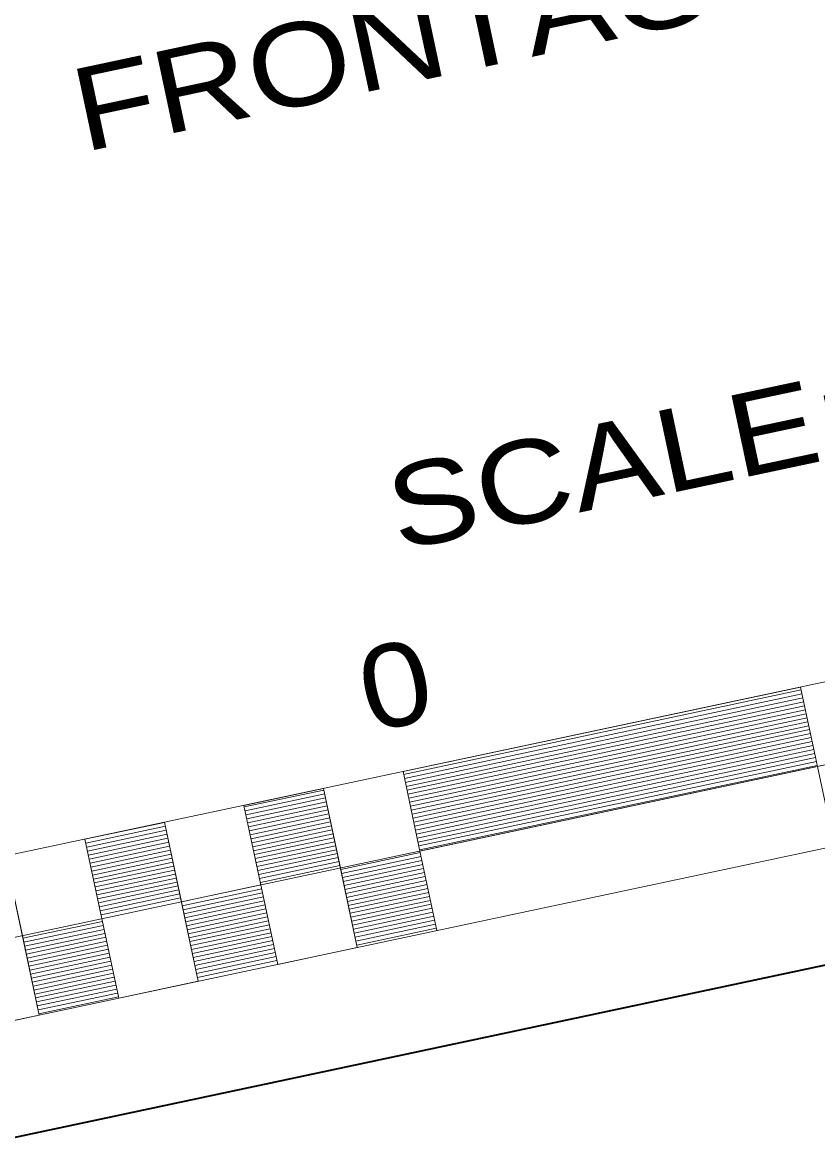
# Model space of a CAD drawing. Extents: x 2357218 to 2371708, y 6973728 to 6980157.
# Drawn here: x 2358141.4 to 2358239.3, y 6974159.6 to 6974296.3 of the extents above; entities that cross this region are included whole.
import ezdxf
from ezdxf.enums import TextEntityAlignment as Align

# ---------------------------------------------------------------- set-up
doc = ezdxf.new("R2010")
doc.units = 0
doc.header["$LTSCALE"] = 2
doc.layers.add('62', color=7, linetype='Continuous', lineweight=13)
doc.layers.add('63', color=7, linetype='Continuous', lineweight=13)

msp = doc.modelspace()

# ---------------------------------------------------------------- linework, layer by layer
at = {"layer": '62', "lineweight": 35}
msp.add_line((2358706.979, 6974279.557), (2358070.155, 6974144.195), dxfattribs=at)
at = {"layer": '62'}
for p, q in [((2358090.44, 6974183.356), (2358481.753, 6974266.532)), ((2358092.52, 6974173.573), (2358483.832, 6974256.749)), ((2358237.181, 6974214.547), (2358239.262, 6974204.763)), ((2358188.343, 6974203.797), (2358237.256, 6974214.195)), ((2358188.446, 6974203.309), (2358237.361, 6974213.706)), ((2358188.551, 6974202.819), (2358237.464, 6974213.216)), ((2358188.656, 6974202.33), (2358237.569, 6974212.727)), ((2358188.758, 6974201.841), (2358237.672, 6974212.237)), ((2358188.862, 6974201.351), (2358237.777, 6974211.748)), ((2358188.966, 6974200.862), (2358237.881, 6974211.259)), ((2358189.07, 6974200.374), (2358237.984, 6974210.769)), ((2358189.175, 6974199.884), (2358238.088, 6974210.281)), ((2358189.279, 6974199.395), (2358238.192, 6974209.792)), ((2358189.382, 6974198.906), (2358238.296, 6974209.302)), ((2358189.487, 6974198.417), (2358238.4, 6974208.814)), ((2358189.591, 6974197.928), (2358238.504, 6974208.324)), ((2358189.694, 6974197.439), (2358238.609, 6974207.836)), ((2358189.798, 6974196.95), (2358238.712, 6974207.346)), ((2358189.902, 6974196.46), (2358238.817, 6974206.857)), ((2358190.006, 6974195.971), (2358238.92, 6974206.368)), ((2358190.11, 6974195.482), (2358239.024, 6974205.88)), ((2358190.215, 6974194.993), (2358239.128, 6974205.39)), ((2358190.319, 6974194.504), (2358239.231, 6974204.902)), ((2358188.269, 6974204.15), (2358190.347, 6974194.367)), ((2358239.262, 6974204.763), (2358241.34, 6974194.981)), ((2358178.486, 6974202.071), (2358180.564, 6974192.289)), ((2358168.744, 6974199.798), (2358178.527, 6974201.878)), ((2358168.847, 6974199.308), (2358178.63, 6974201.388)), ((2358168.951, 6974198.817), (2358178.735, 6974200.898)), ((2358168.702, 6974199.99), (2358170.781, 6974190.208)), ((2358169.055, 6974198.329), (2358178.838, 6974200.41)), ((2358169.16, 6974197.84), (2358178.943, 6974199.92)), ((2358169.264, 6974197.35), (2358179.047, 6974199.431)), ((2358169.367, 6974196.862), (2358179.15, 6974198.941)), ((2358169.471, 6974196.373), (2358179.254, 6974198.452)), ((2358169.575, 6974195.885), (2358179.358, 6974197.964)), ((2358149.139, 6974195.821), (2358158.922, 6974197.901)), ((2358149.242, 6974195.332), (2358159.026, 6974197.411)), ((2358149.347, 6974194.84), (2358159.13, 6974196.921)), ((2358158.92, 6974197.912), (2358160.999, 6974188.129)), ((2358169.68, 6974195.396), (2358179.462, 6974197.474)), ((2358169.784, 6974194.906), (2358179.566, 6974196.985)), ((2358149.136, 6974195.832), (2358151.215, 6974186.05)), ((2358149.452, 6974194.352), (2358159.233, 6974196.433)), ((2358149.555, 6974193.863), (2358159.337, 6974195.943)), ((2358149.659, 6974193.374), (2358159.442, 6974195.454)), ((2358169.887, 6974194.417), (2358179.671, 6974196.495)), ((2358169.992, 6974193.928), (2358179.775, 6974196.007)), ((2358170.096, 6974193.438), (2358179.878, 6974195.517)), ((2358149.763, 6974192.886), (2358159.545, 6974194.964)), ((2358149.866, 6974192.396), (2358159.649, 6974194.475)), ((2358149.971, 6974191.907), (2358159.754, 6974193.986)), ((2358170.199, 6974192.95), (2358179.982, 6974195.029)), ((2358170.303, 6974192.46), (2358180.085, 6974194.539)), ((2358170.406, 6974191.972), (2358180.19, 6974194.049)), ((2358180.605, 6974192.094), (2358190.389, 6974194.174)), ((2358190.347, 6974194.367), (2358192.427, 6974184.585)), ((2358190.348, 6974194.368), (2358192.427, 6974184.584)), ((2358139.354, 6974193.754), (2358141.433, 6974183.97)), ((2358150.075, 6974191.418), (2358159.857, 6974193.497)), ((2358150.178, 6974190.929), (2358159.962, 6974193.008)), ((2358150.282, 6974190.441), (2358160.066, 6974192.518)), ((2358170.511, 6974191.482), (2358180.293, 6974193.561)), ((2358170.614, 6974190.993), (2358180.398, 6974193.072)), ((2358170.719, 6974190.504), (2358180.501, 6974192.583)), ((2358180.71, 6974191.605), (2358190.493, 6974193.684)), ((2358180.813, 6974191.116), (2358190.597, 6974193.196)), ((2358180.917, 6974190.627), (2358190.702, 6974192.708)), ((2358150.386, 6974189.95), (2358160.169, 6974192.03)), ((2358150.491, 6974189.462), (2358160.273, 6974191.541)), ((2358180.564, 6974192.288), (2358182.644, 6974182.505)), ((2358180.565, 6974192.289), (2358182.645, 6974182.506)), ((2358181.021, 6974190.138), (2358190.805, 6974192.217)), ((2358181.125, 6974189.649), (2358190.909, 6974191.729)), ((2358181.23, 6974189.16), (2358191.013, 6974191.239)), ((2358150.594, 6974188.972), (2358160.377, 6974191.052)), ((2358150.698, 6974188.483), (2358160.482, 6974190.563)), ((2358150.803, 6974187.994), (2358160.585, 6974190.074)), ((2358161.001, 6974188.118), (2358170.785, 6974190.198)), ((2358181.333, 6974188.67), (2358191.117, 6974190.75)), ((2358181.437, 6974188.181), (2358191.222, 6974190.261)), ((2358181.541, 6974187.691), (2358191.326, 6974189.772)), ((2358150.906, 6974187.505), (2358160.689, 6974189.584)), ((2358151.011, 6974187.016), (2358160.794, 6974189.096)), ((2358151.115, 6974186.527), (2358160.897, 6974188.606)), ((2358161.106, 6974187.629), (2358170.888, 6974189.709)), ((2358161.209, 6974187.14), (2358170.993, 6974189.22)), ((2358161.313, 6974186.651), (2358171.097, 6974188.731)), ((2358181.644, 6974187.203), (2358191.429, 6974189.284)), ((2358181.749, 6974186.714), (2358191.533, 6974188.794)), ((2358160.998, 6974188.13), (2358163.079, 6974178.346)), ((2358160.999, 6974188.13), (2358163.079, 6974178.347)), ((2358161.416, 6974186.162), (2358171.2, 6974188.241)), ((2358161.521, 6974185.673), (2358171.305, 6974187.752)), ((2358161.625, 6974185.184), (2358171.409, 6974187.263)), ((2358181.853, 6974186.225), (2358191.636, 6974188.305)), ((2358181.957, 6974185.736), (2358191.741, 6974187.817)), ((2358182.061, 6974185.246), (2358191.845, 6974187.325)), ((2358141.505, 6974183.636), (2358151.288, 6974185.714)), ((2358161.728, 6974184.694), (2358171.513, 6974186.774)), ((2358161.832, 6974184.205), (2358171.616, 6974186.285)), ((2358161.936, 6974183.716), (2358171.72, 6974185.796)), ((2358182.165, 6974184.758), (2358191.949, 6974186.837)), ((2358182.27, 6974184.269), (2358192.053, 6974186.347)), ((2358182.373, 6974183.779), (2358192.157, 6974185.858)), ((2358141.608, 6974183.145), (2358151.392, 6974185.225)), ((2358141.712, 6974182.657), (2358151.497, 6974184.736)), ((2358162.041, 6974183.227), (2358171.825, 6974185.307)), ((2358162.145, 6974182.738), (2358171.928, 6974184.818)), ((2358162.248, 6974182.249), (2358172.033, 6974184.329)), ((2358182.477, 6974183.29), (2358192.26, 6974185.37)), ((2358182.581, 6974182.8), (2358192.365, 6974184.88)), ((2358141.433, 6974183.971), (2358143.512, 6974174.188)), ((2358141.433, 6974183.97), (2358143.513, 6974174.187)), ((2358141.817, 6974182.168), (2358151.6, 6974184.247)), ((2358141.92, 6974181.678), (2358151.705, 6974183.758)), ((2358142.023, 6974181.19), (2358151.808, 6974183.268)), ((2358162.353, 6974181.76), (2358172.137, 6974183.84)), ((2358162.457, 6974181.27), (2358172.24, 6974183.349)), ((2358142.128, 6974180.7), (2358151.911, 6974182.779)), ((2358142.232, 6974180.211), (2358152.015, 6974182.29)), ((2358142.335, 6974179.723), (2358152.119, 6974181.801)), ((2358162.561, 6974180.781), (2358172.345, 6974182.861)), ((2358162.665, 6974180.293), (2358172.448, 6974182.371)), ((2358162.768, 6974179.803), (2358172.553, 6974181.882)), ((2358142.44, 6974179.233), (2358152.223, 6974181.312)), ((2358142.544, 6974178.744), (2358152.328, 6974180.822)), ((2358142.647, 6974178.254), (2358152.431, 6974180.335)), ((2358162.873, 6974179.315), (2358172.656, 6974181.393)), ((2358162.976, 6974178.824), (2358172.76, 6974180.904)), ((2358142.752, 6974177.766), (2358152.536, 6974179.846)), ((2358142.854, 6974177.276), (2358152.639, 6974179.357)), ((2358142.959, 6974176.786), (2358152.743, 6974178.867)), ((2358143.063, 6974176.297), (2358152.847, 6974178.377)), ((2358143.167, 6974175.808), (2358152.951, 6974177.889)), ((2358143.271, 6974175.319), (2358153.056, 6974177.4)), ((2358143.376, 6974174.829), (2358153.159, 6974176.909)), ((2358143.479, 6974174.341), (2358153.264, 6974176.421))]:
    msp.add_line(p, q, dxfattribs=at)
for points in [[(2358190.347, 6974194.367), (2358239.262, 6974204.763), (2358237.181, 6974214.547), (2358188.269, 6974204.15)], [(2358241.34, 6974194.981), (2358290.254, 6974205.378), (2358288.175, 6974215.161), (2358239.262, 6974204.763)], [(2358172.861, 6974180.425), (2358182.644, 6974182.505), (2358178.486, 6974202.071), (2358168.702, 6974199.99)], [(2358153.296, 6974176.266), (2358163.079, 6974178.346), (2358158.92, 6974197.912), (2358149.136, 6974195.832)], [(2358133.73, 6974172.108), (2358143.513, 6974174.187), (2358139.354, 6974193.754), (2358129.57, 6974191.674)]]:
    msp.add_lwpolyline(points, close=True, dxfattribs=at)
at = {"layer": '63'}
for p, q in [((2358090.44, 6974183.356), (2358481.753, 6974266.532)), ((2358092.52, 6974173.573), (2358483.832, 6974256.749)), ((2358094.598, 6974163.791), (2358485.911, 6974246.966)), ((2358237.181, 6974214.547), (2358239.262, 6974204.763)), ((2358188.343, 6974203.797), (2358237.256, 6974214.195)), ((2358188.446, 6974203.309), (2358237.361, 6974213.706)), ((2358188.551, 6974202.819), (2358237.464, 6974213.216)), ((2358188.656, 6974202.33), (2358237.569, 6974212.727)), ((2358188.758, 6974201.841), (2358237.672, 6974212.237)), ((2358188.862, 6974201.351), (2358237.777, 6974211.748)), ((2358188.966, 6974200.862), (2358237.881, 6974211.259)), ((2358189.07, 6974200.374), (2358237.984, 6974210.769)), ((2358189.175, 6974199.884), (2358238.088, 6974210.281)), ((2358189.279, 6974199.395), (2358238.192, 6974209.792)), ((2358189.382, 6974198.906), (2358238.296, 6974209.302)), ((2358189.487, 6974198.417), (2358238.4, 6974208.814)), ((2358189.591, 6974197.928), (2358238.504, 6974208.324)), ((2358189.694, 6974197.439), (2358238.609, 6974207.836)), ((2358189.798, 6974196.95), (2358238.712, 6974207.346)), ((2358189.902, 6974196.46), (2358238.817, 6974206.857)), ((2358190.006, 6974195.971), (2358238.92, 6974206.368)), ((2358190.11, 6974195.482), (2358239.024, 6974205.88)), ((2358190.215, 6974194.993), (2358239.128, 6974205.39)), ((2358190.319, 6974194.504), (2358239.231, 6974204.902)), ((2358188.269, 6974204.15), (2358190.347, 6974194.367)), ((2358239.262, 6974204.763), (2358241.34, 6974194.981)), ((2358178.486, 6974202.071), (2358180.564, 6974192.289)), ((2358168.744, 6974199.798), (2358178.527, 6974201.878)), ((2358168.847, 6974199.308), (2358178.63, 6974201.388)), ((2358168.951, 6974198.817), (2358178.735, 6974200.898)), ((2358168.702, 6974199.99), (2358170.781, 6974190.208)), ((2358169.055, 6974198.329), (2358178.838, 6974200.41)), ((2358169.16, 6974197.84), (2358178.943, 6974199.92)), ((2358169.264, 6974197.35), (2358179.047, 6974199.431)), ((2358169.367, 6974196.862), (2358179.15, 6974198.941)), ((2358169.471, 6974196.373), (2358179.254, 6974198.452)), ((2358169.575, 6974195.885), (2358179.358, 6974197.964)), ((2358149.139, 6974195.821), (2358158.922, 6974197.901)), ((2358149.242, 6974195.332), (2358159.026, 6974197.411)), ((2358149.347, 6974194.84), (2358159.13, 6974196.921)), ((2358158.92, 6974197.912), (2358160.999, 6974188.129)), ((2358169.68, 6974195.396), (2358179.462, 6974197.474)), ((2358169.784, 6974194.906), (2358179.566, 6974196.985)), ((2358149.136, 6974195.832), (2358151.215, 6974186.05)), ((2358149.452, 6974194.352), (2358159.233, 6974196.433)), ((2358149.555, 6974193.863), (2358159.337, 6974195.943)), ((2358149.659, 6974193.374), (2358159.442, 6974195.454)), ((2358169.887, 6974194.417), (2358179.671, 6974196.495)), ((2358169.992, 6974193.928), (2358179.775, 6974196.007)), ((2358170.096, 6974193.438), (2358179.878, 6974195.517)), ((2358149.763, 6974192.886), (2358159.545, 6974194.964)), ((2358149.866, 6974192.396), (2358159.649, 6974194.475)), ((2358149.971, 6974191.907), (2358159.754, 6974193.986)), ((2358170.199, 6974192.95), (2358179.982, 6974195.029)), ((2358170.303, 6974192.46), (2358180.085, 6974194.539)), ((2358170.406, 6974191.972), (2358180.19, 6974194.049)), ((2358180.605, 6974192.094), (2358190.389, 6974194.174)), ((2358190.347, 6974194.367), (2358192.427, 6974184.585)), ((2358190.348, 6974194.368), (2358192.427, 6974184.584)), ((2358139.354, 6974193.754), (2358141.433, 6974183.97)), ((2358150.075, 6974191.418), (2358159.857, 6974193.497)), ((2358150.178, 6974190.929), (2358159.962, 6974193.008)), ((2358150.282, 6974190.441), (2358160.066, 6974192.518)), ((2358170.511, 6974191.482), (2358180.293, 6974193.561)), ((2358170.614, 6974190.993), (2358180.398, 6974193.072)), ((2358170.719, 6974190.504), (2358180.501, 6974192.583)), ((2358180.71, 6974191.605), (2358190.493, 6974193.684)), ((2358180.813, 6974191.116), (2358190.597, 6974193.196)), ((2358180.917, 6974190.627), (2358190.702, 6974192.708)), ((2358150.386, 6974189.95), (2358160.169, 6974192.03)), ((2358150.491, 6974189.462), (2358160.273, 6974191.541)), ((2358180.564, 6974192.288), (2358182.644, 6974182.505)), ((2358180.565, 6974192.289), (2358182.645, 6974182.506)), ((2358181.021, 6974190.138), (2358190.805, 6974192.217)), ((2358181.125, 6974189.649), (2358190.909, 6974191.729)), ((2358181.23, 6974189.16), (2358191.013, 6974191.239)), ((2358150.594, 6974188.972), (2358160.377, 6974191.052)), ((2358150.698, 6974188.483), (2358160.482, 6974190.563)), ((2358150.803, 6974187.994), (2358160.585, 6974190.074)), ((2358161.001, 6974188.118), (2358170.785, 6974190.198)), ((2358181.333, 6974188.67), (2358191.117, 6974190.75)), ((2358181.437, 6974188.181), (2358191.222, 6974190.261)), ((2358181.541, 6974187.691), (2358191.326, 6974189.772)), ((2358150.906, 6974187.505), (2358160.689, 6974189.584)), ((2358151.011, 6974187.016), (2358160.794, 6974189.096)), ((2358151.115, 6974186.527), (2358160.897, 6974188.606)), ((2358161.106, 6974187.629), (2358170.888, 6974189.709)), ((2358161.209, 6974187.14), (2358170.993, 6974189.22)), ((2358161.313, 6974186.651), (2358171.097, 6974188.731)), ((2358181.644, 6974187.203), (2358191.429, 6974189.284)), ((2358181.749, 6974186.714), (2358191.533, 6974188.794)), ((2358160.998, 6974188.13), (2358163.079, 6974178.346)), ((2358160.999, 6974188.13), (2358163.079, 6974178.347)), ((2358161.416, 6974186.162), (2358171.2, 6974188.241)), ((2358161.521, 6974185.673), (2358171.305, 6974187.752)), ((2358161.625, 6974185.184), (2358171.409, 6974187.263)), ((2358181.853, 6974186.225), (2358191.636, 6974188.305)), ((2358181.957, 6974185.736), (2358191.741, 6974187.817)), ((2358182.061, 6974185.246), (2358191.845, 6974187.325)), ((2358141.505, 6974183.636), (2358151.288, 6974185.714)), ((2358161.728, 6974184.694), (2358171.513, 6974186.774)), ((2358161.832, 6974184.205), (2358171.616, 6974186.285)), ((2358161.936, 6974183.716), (2358171.72, 6974185.796)), ((2358182.165, 6974184.758), (2358191.949, 6974186.837)), ((2358182.27, 6974184.269), (2358192.053, 6974186.347)), ((2358182.373, 6974183.779), (2358192.157, 6974185.858)), ((2358141.608, 6974183.145), (2358151.392, 6974185.225)), ((2358141.712, 6974182.657), (2358151.497, 6974184.736)), ((2358162.041, 6974183.227), (2358171.825, 6974185.307)), ((2358162.145, 6974182.738), (2358171.928, 6974184.818)), ((2358162.248, 6974182.249), (2358172.033, 6974184.329)), ((2358182.477, 6974183.29), (2358192.26, 6974185.37)), ((2358182.581, 6974182.8), (2358192.365, 6974184.88)), ((2358141.433, 6974183.971), (2358143.512, 6974174.188)), ((2358141.433, 6974183.97), (2358143.513, 6974174.187)), ((2358141.817, 6974182.168), (2358151.6, 6974184.247)), ((2358141.92, 6974181.678), (2358151.705, 6974183.758)), ((2358142.023, 6974181.19), (2358151.808, 6974183.268)), ((2358162.353, 6974181.76), (2358172.137, 6974183.84)), ((2358162.457, 6974181.27), (2358172.24, 6974183.349)), ((2358142.128, 6974180.7), (2358151.911, 6974182.779)), ((2358142.232, 6974180.211), (2358152.015, 6974182.29)), ((2358142.335, 6974179.723), (2358152.119, 6974181.801)), ((2358162.561, 6974180.781), (2358172.345, 6974182.861)), ((2358162.665, 6974180.293), (2358172.448, 6974182.371)), ((2358162.768, 6974179.803), (2358172.553, 6974181.882)), ((2358142.44, 6974179.233), (2358152.223, 6974181.312)), ((2358142.544, 6974178.744), (2358152.328, 6974180.822)), ((2358142.647, 6974178.254), (2358152.431, 6974180.335)), ((2358162.873, 6974179.315), (2358172.656, 6974181.393)), ((2358162.976, 6974178.824), (2358172.76, 6974180.904)), ((2358142.752, 6974177.766), (2358152.536, 6974179.846)), ((2358142.854, 6974177.276), (2358152.639, 6974179.357)), ((2358142.959, 6974176.786), (2358152.743, 6974178.867)), ((2358143.063, 6974176.297), (2358152.847, 6974178.377)), ((2358143.167, 6974175.808), (2358152.951, 6974177.889)), ((2358143.271, 6974175.319), (2358153.056, 6974177.4)), ((2358143.376, 6974174.829), (2358153.159, 6974176.909)), ((2358143.479, 6974174.341), (2358153.264, 6974176.421))]:
    msp.add_line(p, q, dxfattribs=at)
for points in [[(2358190.347, 6974194.367), (2358239.262, 6974204.763), (2358237.181, 6974214.547), (2358188.269, 6974204.15)], [(2358241.34, 6974194.981), (2358290.254, 6974205.378), (2358288.175, 6974215.161), (2358239.262, 6974204.763)], [(2358172.861, 6974180.425), (2358182.644, 6974182.505), (2358178.486, 6974202.071), (2358168.702, 6974199.99)], [(2358153.296, 6974176.266), (2358163.079, 6974178.346), (2358158.92, 6974197.912), (2358149.136, 6974195.832)], [(2358133.73, 6974172.108), (2358143.513, 6974174.187), (2358139.354, 6974193.754), (2358129.57, 6974191.674)]]:
    msp.add_lwpolyline(points, close=True, dxfattribs=at)

# ---------------------------------------------------------------- texts
at = {"layer": '62'}
for s, width, p in [('FRONTAGE ROAD DESIGN SPEED VARIABLE 35 TO 40 MPH', 1.2, (2358378.055, 6974329.019)), ('SCALE:  1 INCH = 100 FT.', 1.2, (2358283.549, 6974251.641)), ('0', 1.15, (2358188.389, 6974209.834))]:
    msp.add_text(s, height=10.2, rotation=12, dxfattribs=dict(at, width=width)).set_placement(p, align=Align.CENTER)
at = {"layer": '63', "width": 1.15}
msp.add_text('0', height=10.2, rotation=12, dxfattribs=at).set_placement((2358188.389, 6974209.834), align=Align.CENTER)

doc.saveas('drawing.dxf')
